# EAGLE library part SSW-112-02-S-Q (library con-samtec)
THROUGH-HOLE .025" SQ POST SOCKET Source: Samtec SSW.pdf
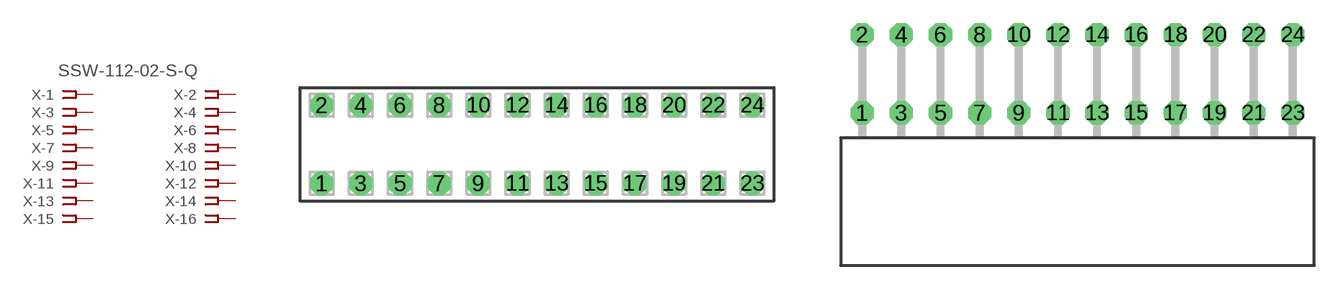
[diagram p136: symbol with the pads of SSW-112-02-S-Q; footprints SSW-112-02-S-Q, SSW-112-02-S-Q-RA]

Designator prefix X; gates -1=FPINV -2=FPIN -3=FPIN -4=FPIN -5=FPIN -6=FPIN -7=FPIN -8=FPIN -9=FPIN -10=FPIN -11=FPIN -12=FPIN -13=FPIN -14=FPIN -15=FPIN -16=FPIN -17=FPIN -18=FPIN -19=FPIN -20=FPIN -21=FPIN -22=FPIN -23=FPIN -24=FPIN

## SSW-112-02-S-Q (MPN: SSW-112-02-S-Q; OC_FARNELL: unknown; OC_NEWARK: 82P5875)  [SSW-112-02-S-Q]
1  -1:1  pas
2  -2:1  pas
3  -3:1  pas
4  -4:1  pas
5  -5:1  pas
6  -6:1  pas
7  -7:1  pas
8  -8:1  pas
9  -9:1  pas
10  -10:1  pas
11  -11:1  pas
12  -12:1  pas
13  -13:1  pas
14  -14:1  pas
15  -15:1  pas
16  -16:1  pas
17  -17:1  pas
18  -18:1  pas
19  -19:1  pas
20  -20:1  pas
21  -21:1  pas
22  -22:1  pas
23  -23:1  pas
24  -24:1  pas

## SSW-112-02-S-QRA (MPN: SSW-112-02-S-Q-RA; OC_FARNELL: unknown; OC_NEWARK: 82P5876)  [SSW-112-02-S-Q-RA]
Pads as for SSW-112-02-S-Q

## Footprint SSW-112-02-S-Q (pad centres in mm)
THROUGH-HOLE .025" SQ POST SOCKET Source: Samtec SSW.pdf
drill 1 pad 1.5 octagon: 1 -13.97,-2.54; 2 -13.97,2.54; 3 -11.43,-2.54; 4 -11.43,2.54; 5 -8.89,-2.54; 6 -8.89,2.54; 7 -6.35,-2.54; 8 -6.35,2.54; 9 -3.81,-2.54; 10 -3.81,2.54; 11 -1.27,-2.54; 12 -1.27,2.54; 13 1.27,-2.54; 14 1.27,2.54; 15 3.81,-2.54; 16 3.81,2.54; 17 6.35,-2.54; 18 6.35,2.54; 19 8.89,-2.54; 20 8.89,2.54; 21 11.43,-2.54; 22 11.43,2.54; 23 13.97,-2.54; 24 13.97,2.54

## Footprint SSW-112-02-S-Q-RA (pad centres in mm)
THROUGH-HOLE .025" SQ POST SOCKET Source: Samtec SSW.pdf
drill 1 pad 1.5 octagon: 1 -13.97,1.524; 2 -13.97,6.604; 3 -11.43,1.524; 4 -11.43,6.604; 5 -8.89,1.524; 6 -8.89,6.604; 7 -6.35,1.524; 8 -6.35,6.604; 9 -3.81,1.524; 10 -3.81,6.604; 11 -1.27,1.524; 12 -1.27,6.604; 13 1.27,1.524; 14 1.27,6.604; 15 3.81,1.524; 16 3.81,6.604; 17 6.35,1.524; 18 6.35,6.604; 19 8.89,1.524; 20 8.89,6.604; 21 11.43,1.524; 22 11.43,6.604; 23 13.97,1.524; 24 13.97,6.604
